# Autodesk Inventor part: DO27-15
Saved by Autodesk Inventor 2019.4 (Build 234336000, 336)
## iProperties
Created: 2020-04
Part Number: DO27-15
Material: Generic
Document SubType Name: Modeling
Designer: Administrator
Density: 1 g/cm^3
Appearance: Default
Title: DO27-15
Author: Administrator
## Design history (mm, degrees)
feature "Body2"
body "Solid1"
